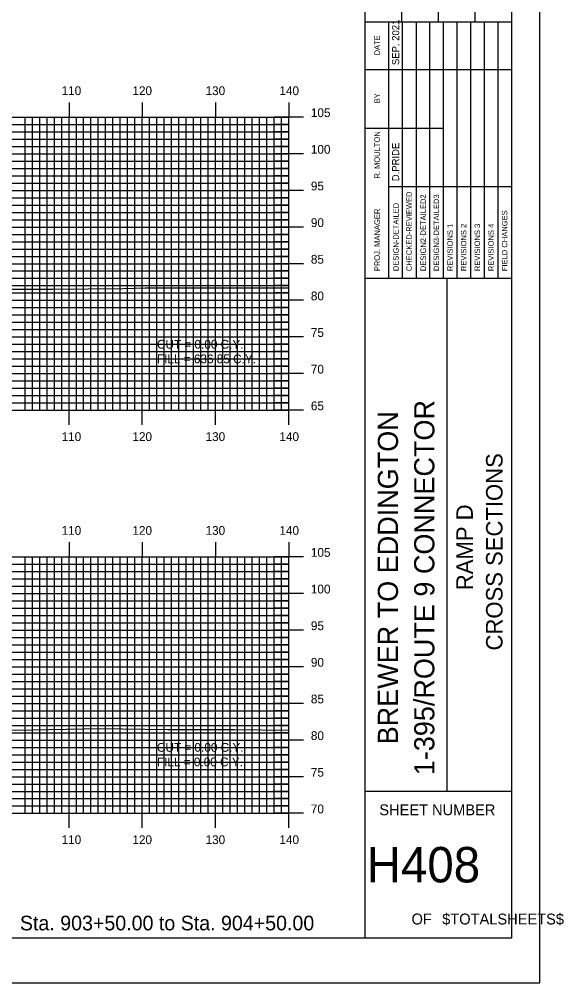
# Model space of a CAD drawing. Extents: x 857110 to 857453, y 364765 to 364985.
# Drawn here: x 857379 to 857453.3, y 364765.2 to 364896.6 of the extents above; entities that cross this region are included whole.
import ezdxf

# ---------------------------------------------------------------- set-up
doc = ezdxf.new("R2010")
doc.units = 0
for name, color, linetype in [('BORDER', 7, 'Continuous'), ('D_Text_Standard', 7, 'Continuous'), ('H_V ANNOTATION', 7, 'Continuous'), ('MAJOR', 7, 'Continuous'), ('MINOR', 7, 'Continuous'), ('PLOT BOUNDARY', 7, 'Continuous'), ('S_Roadway_Centerline', 7, 'Continuous')]:
    doc.layers.add(name, color=color, linetype=linetype)

msp = doc.modelspace()

# ---------------------------------------------------------------- linework, layer by layer
at = {"layer": 'BORDER'}
for p, q in [((857426.19, 364771.3), (857426.19, 364981.3)), ((857431.19, 364896.31), (857431.19, 364913.6)), ((857436.19, 364896.31), (857436.19, 364913.6)), ((857441.19, 364896.31), (857441.19, 364913.6)), ((857426.19, 364896.31), (857446.19, 364896.31)), ((857426.19, 364861.31), (857446.19, 364861.31)), ((857437.38, 364791.31), (857437.38, 364861.31)), ((857426.19, 364791.31), (857446.19, 364791.31))]:
    msp.add_line(p, q, dxfattribs=at)
msp.add_lwpolyline([(857126.19, 364771.3), (857446.19, 364771.3), (857446.19, 364981.3), (857126.19, 364981.3)], close=True, dxfattribs=at)
for points in [[(857429.42, 364889.81), (857429.42, 364896.31)], [(857431.29, 364861.31), (857431.29, 364896.31)], [(857433.15, 364896.31), (857433.15, 364861.31)], [(857435.02, 364861.31), (857435.02, 364896.31)], [(857436.88, 364861.31), (857436.88, 364896.31)], [(857438.74, 364861.31), (857438.74, 364896.31)], [(857440.61, 364861.31), (857440.61, 364896.31)], [(857442.47, 364861.31), (857442.47, 364896.31)], [(857444.33, 364861.31), (857444.33, 364896.31)], [(857429.43, 364861.31), (857429.43, 364894.9)], [(857426.19, 364889.81), (857446.19, 364889.81)], [(857426.19, 364881.81), (857429.43, 364881.81)], [(857429.42, 364881.81), (857436.88, 364881.81)], [(857429.42, 364873.81), (857446.19, 364873.81)]]:
    msp.add_lwpolyline(points, dxfattribs=at)
at = {"layer": 'MAJOR'}
for p, q in [((857385.79, 364885.31), (857385.79, 364883.3)), ((857395.79, 364885.31), (857395.79, 364883.3)), ((857405.79, 364885.31), (857405.79, 364883.3)), ((857415.79, 364885.31), (857415.79, 364883.3)), ((857135.79, 364883.3), (857415.79, 364883.3)), ((857135.79, 364883.3), (857415.79, 364883.3)), ((857385.79, 364843.3), (857385.79, 364883.3)), ((857395.79, 364843.3), (857395.79, 364883.3)), ((857405.79, 364843.3), (857405.79, 364883.3)), ((857417.8, 364883.3), (857413.79, 364883.3)), ((857415.79, 364843.3), (857415.79, 364883.3)), ((857415.79, 364843.3), (857415.79, 364883.3)), ((857135.79, 364878.3), (857415.79, 364878.3)), ((857417.8, 364878.3), (857413.79, 364878.3)), ((857135.79, 364873.3), (857415.79, 364873.3)), ((857417.8, 364873.3), (857413.79, 364873.3)), ((857135.79, 364868.3), (857415.79, 364868.3)), ((857417.8, 364868.3), (857413.79, 364868.3)), ((857135.79, 364863.3), (857415.79, 364863.3)), ((857417.8, 364863.3), (857413.79, 364863.3)), ((857135.79, 364858.3), (857415.79, 364858.3)), ((857417.8, 364858.3), (857413.79, 364858.3)), ((857135.79, 364853.3), (857415.79, 364853.3)), ((857417.8, 364853.3), (857413.79, 364853.3)), ((857135.79, 364848.3), (857415.79, 364848.3)), ((857417.8, 364848.3), (857413.79, 364848.3)), ((857135.79, 364843.3), (857415.79, 364843.3)), ((857135.79, 364843.3), (857415.79, 364843.3)), ((857385.79, 364841.3), (857385.79, 364843.3)), ((857395.79, 364841.3), (857395.79, 364843.3)), ((857405.79, 364841.3), (857405.79, 364843.3)), ((857417.8, 364843.3), (857413.79, 364843.3)), ((857415.79, 364841.3), (857415.79, 364843.3)), ((857385.79, 364825.31), (857385.79, 364823.3)), ((857395.79, 364825.31), (857395.79, 364823.3)), ((857405.79, 364825.31), (857405.79, 364823.3)), ((857415.79, 364825.31), (857415.79, 364823.3)), ((857135.79, 364823.3), (857415.79, 364823.3)), ((857135.79, 364823.3), (857415.79, 364823.3)), ((857385.79, 364788.3), (857385.79, 364823.3)), ((857395.79, 364788.3), (857395.79, 364823.3)), ((857405.79, 364788.3), (857405.79, 364823.3)), ((857417.8, 364823.3), (857413.79, 364823.3)), ((857415.79, 364788.3), (857415.79, 364823.3)), ((857415.79, 364788.3), (857415.79, 364823.3)), ((857135.79, 364818.3), (857415.79, 364818.3)), ((857417.8, 364818.3), (857413.79, 364818.3)), ((857135.79, 364813.3), (857415.79, 364813.3)), ((857417.8, 364813.3), (857413.79, 364813.3)), ((857135.79, 364808.3), (857415.79, 364808.3)), ((857417.8, 364808.3), (857413.79, 364808.3)), ((857135.79, 364803.3), (857415.79, 364803.3)), ((857417.8, 364803.3), (857413.79, 364803.3)), ((857135.79, 364798.3), (857415.79, 364798.3)), ((857417.8, 364798.3), (857413.79, 364798.3)), ((857135.79, 364793.3), (857415.79, 364793.3)), ((857417.8, 364793.3), (857413.79, 364793.3)), ((857135.79, 364788.3), (857415.79, 364788.3)), ((857135.79, 364788.3), (857415.79, 364788.3)), ((857385.79, 364786.3), (857385.79, 364788.3)), ((857395.79, 364786.3), (857395.79, 364788.3)), ((857405.79, 364786.3), (857405.79, 364788.3)), ((857417.8, 364788.3), (857413.79, 364788.3)), ((857415.79, 364786.3), (857415.79, 364788.3))]:
    msp.add_line(p, q, dxfattribs=at)
at = {"layer": 'MINOR'}
for p, q in [((857379.79, 364843.3), (857379.79, 364883.3)), ((857380.79, 364843.3), (857380.79, 364883.3)), ((857381.79, 364843.3), (857381.79, 364883.3)), ((857382.79, 364843.3), (857382.79, 364883.3)), ((857383.79, 364843.3), (857383.79, 364883.3)), ((857384.79, 364843.3), (857384.79, 364883.3)), ((857386.79, 364843.3), (857386.79, 364883.3)), ((857387.79, 364843.3), (857387.79, 364883.3)), ((857388.79, 364843.3), (857388.79, 364883.3)), ((857389.79, 364843.3), (857389.79, 364883.3)), ((857390.79, 364843.3), (857390.79, 364883.3)), ((857391.79, 364843.3), (857391.79, 364883.3)), ((857392.79, 364843.3), (857392.79, 364883.3)), ((857393.79, 364843.3), (857393.79, 364883.3)), ((857394.79, 364843.3), (857394.79, 364883.3)), ((857396.79, 364843.3), (857396.79, 364883.3)), ((857397.79, 364843.3), (857397.79, 364883.3)), ((857398.79, 364843.3), (857398.79, 364883.3)), ((857399.79, 364843.3), (857399.79, 364883.3)), ((857400.79, 364843.3), (857400.79, 364883.3)), ((857401.79, 364843.3), (857401.79, 364883.3)), ((857402.79, 364843.3), (857402.79, 364883.3)), ((857403.79, 364843.3), (857403.79, 364883.3)), ((857404.79, 364843.3), (857404.79, 364883.3)), ((857406.79, 364843.3), (857406.79, 364883.3)), ((857407.79, 364843.3), (857407.79, 364883.3)), ((857408.79, 364843.3), (857408.79, 364883.3)), ((857409.79, 364843.3), (857409.79, 364883.3)), ((857410.79, 364843.3), (857410.79, 364883.3)), ((857411.79, 364843.3), (857411.79, 364883.3)), ((857412.79, 364843.3), (857412.79, 364883.3)), ((857413.79, 364843.3), (857413.79, 364883.3)), ((857414.79, 364843.3), (857414.79, 364883.3)), ((857135.79, 364882.3), (857415.79, 364882.3)), ((857415.79, 364882.3), (857413.79, 364882.3)), ((857135.79, 364881.3), (857415.79, 364881.3)), ((857135.79, 364880.3), (857415.79, 364880.3)), ((857415.79, 364881.3), (857413.79, 364881.3)), ((857415.79, 364880.3), (857413.79, 364880.3)), ((857135.79, 364879.3), (857415.79, 364879.3)), ((857415.79, 364879.3), (857413.79, 364879.3)), ((857135.79, 364877.3), (857415.79, 364877.3)), ((857135.79, 364876.3), (857415.79, 364876.3)), ((857415.79, 364877.3), (857413.79, 364877.3)), ((857415.79, 364876.3), (857413.79, 364876.3)), ((857135.79, 364875.3), (857415.79, 364875.3)), ((857415.79, 364875.3), (857413.79, 364875.3)), ((857135.79, 364874.3), (857415.79, 364874.3)), ((857415.79, 364874.3), (857413.79, 364874.3)), ((857135.79, 364872.3), (857415.79, 364872.3)), ((857415.79, 364872.3), (857413.79, 364872.3)), ((857135.79, 364871.3), (857415.79, 364871.3)), ((857415.79, 364871.3), (857413.79, 364871.3)), ((857135.79, 364870.3), (857415.79, 364870.3)), ((857415.79, 364870.3), (857413.79, 364870.3)), ((857135.79, 364869.3), (857415.79, 364869.3)), ((857415.79, 364869.3), (857413.79, 364869.3)), ((857135.79, 364867.3), (857415.79, 364867.3)), ((857415.79, 364867.3), (857413.79, 364867.3)), ((857135.79, 364866.3), (857415.79, 364866.3)), ((857415.79, 364866.3), (857413.79, 364866.3)), ((857135.79, 364865.3), (857415.79, 364865.3)), ((857135.79, 364864.3), (857415.79, 364864.3)), ((857415.79, 364865.3), (857413.79, 364865.3)), ((857415.79, 364864.3), (857413.79, 364864.3)), ((857135.79, 364862.3), (857415.79, 364862.3)), ((857415.79, 364862.3), (857413.79, 364862.3)), ((857135.79, 364861.3), (857415.79, 364861.3)), ((857135.79, 364860.3), (857415.79, 364860.3)), ((857415.79, 364861.3), (857413.79, 364861.3)), ((857415.79, 364860.3), (857413.79, 364860.3)), ((857135.79, 364859.3), (857415.79, 364859.3)), ((857415.79, 364859.3), (857413.79, 364859.3)), ((857135.79, 364857.3), (857415.79, 364857.3)), ((857415.79, 364857.3), (857413.79, 364857.3)), ((857135.79, 364856.3), (857415.79, 364856.3)), ((857135.79, 364855.3), (857415.79, 364855.3)), ((857415.79, 364856.3), (857413.79, 364856.3)), ((857415.79, 364855.3), (857413.79, 364855.3)), ((857135.79, 364854.3), (857415.79, 364854.3)), ((857415.79, 364854.3), (857413.79, 364854.3)), ((857135.79, 364852.3), (857415.79, 364852.3)), ((857135.79, 364851.3), (857415.79, 364851.3)), ((857415.79, 364852.3), (857413.79, 364852.3)), ((857415.79, 364851.3), (857413.79, 364851.3)), ((857135.79, 364850.3), (857415.79, 364850.3)), ((857415.79, 364850.3), (857413.79, 364850.3)), ((857135.79, 364849.3), (857415.79, 364849.3)), ((857415.79, 364849.3), (857413.79, 364849.3)), ((857135.79, 364847.3), (857415.79, 364847.3)), ((857415.79, 364847.3), (857413.79, 364847.3)), ((857135.79, 364846.3), (857415.79, 364846.3)), ((857415.79, 364846.3), (857413.79, 364846.3)), ((857135.79, 364845.3), (857415.79, 364845.3)), ((857415.79, 364845.3), (857413.79, 364845.3)), ((857135.79, 364844.3), (857415.79, 364844.3)), ((857415.79, 364844.3), (857413.79, 364844.3)), ((857135.79, 364822.3), (857415.79, 364822.3)), ((857379.79, 364788.3), (857379.79, 364823.3)), ((857380.79, 364788.3), (857380.79, 364823.3)), ((857381.79, 364788.3), (857381.79, 364823.3)), ((857382.79, 364788.3), (857382.79, 364823.3)), ((857383.79, 364788.3), (857383.79, 364823.3)), ((857384.79, 364788.3), (857384.79, 364823.3)), ((857386.79, 364788.3), (857386.79, 364823.3)), ((857387.79, 364788.3), (857387.79, 364823.3)), ((857388.79, 364788.3), (857388.79, 364823.3)), ((857389.79, 364788.3), (857389.79, 364823.3)), ((857390.79, 364788.3), (857390.79, 364823.3)), ((857391.79, 364788.3), (857391.79, 364823.3)), ((857392.79, 364788.3), (857392.79, 364823.3)), ((857393.79, 364788.3), (857393.79, 364823.3)), ((857394.79, 364788.3), (857394.79, 364823.3)), ((857396.79, 364788.3), (857396.79, 364823.3)), ((857397.79, 364788.3), (857397.79, 364823.3)), ((857398.79, 364788.3), (857398.79, 364823.3)), ((857399.79, 364788.3), (857399.79, 364823.3)), ((857400.79, 364788.3), (857400.79, 364823.3)), ((857401.79, 364788.3), (857401.79, 364823.3)), ((857402.79, 364788.3), (857402.79, 364823.3)), ((857403.79, 364788.3), (857403.79, 364823.3)), ((857404.79, 364788.3), (857404.79, 364823.3)), ((857406.79, 364788.3), (857406.79, 364823.3)), ((857407.79, 364788.3), (857407.79, 364823.3)), ((857408.79, 364788.3), (857408.79, 364823.3)), ((857409.79, 364788.3), (857409.79, 364823.3)), ((857410.79, 364788.3), (857410.79, 364823.3)), ((857411.79, 364788.3), (857411.79, 364823.3)), ((857412.79, 364788.3), (857412.79, 364823.3)), ((857413.79, 364788.3), (857413.79, 364823.3)), ((857415.79, 364822.3), (857413.79, 364822.3)), ((857414.79, 364788.3), (857414.79, 364823.3)), ((857135.79, 364821.3), (857415.79, 364821.3)), ((857415.79, 364821.3), (857413.79, 364821.3)), ((857135.79, 364820.3), (857415.79, 364820.3)), ((857415.79, 364820.3), (857413.79, 364820.3)), ((857135.79, 364819.3), (857415.79, 364819.3)), ((857415.79, 364819.3), (857413.79, 364819.3)), ((857135.79, 364817.3), (857415.79, 364817.3)), ((857415.79, 364817.3), (857413.79, 364817.3)), ((857135.79, 364816.3), (857415.79, 364816.3)), ((857415.79, 364816.3), (857413.79, 364816.3)), ((857135.79, 364815.3), (857415.79, 364815.3)), ((857135.79, 364814.3), (857415.79, 364814.3)), ((857415.79, 364815.3), (857413.79, 364815.3)), ((857415.79, 364814.3), (857413.79, 364814.3)), ((857135.79, 364812.3), (857415.79, 364812.3)), ((857415.79, 364812.3), (857413.79, 364812.3)), ((857135.79, 364811.3), (857415.79, 364811.3)), ((857415.79, 364811.3), (857413.79, 364811.3)), ((857135.79, 364810.3), (857415.79, 364810.3)), ((857135.79, 364809.3), (857415.79, 364809.3)), ((857415.79, 364810.3), (857413.79, 364810.3)), ((857415.79, 364809.3), (857413.79, 364809.3)), ((857135.79, 364807.3), (857415.79, 364807.3)), ((857415.79, 364807.3), (857413.79, 364807.3)), ((857135.79, 364806.3), (857415.79, 364806.3)), ((857135.79, 364805.3), (857415.79, 364805.3)), ((857415.79, 364806.3), (857413.79, 364806.3)), ((857415.79, 364805.3), (857413.79, 364805.3)), ((857135.79, 364804.3), (857415.79, 364804.3)), ((857415.79, 364804.3), (857413.79, 364804.3)), ((857135.79, 364802.3), (857415.79, 364802.3)), ((857135.79, 364801.3), (857415.79, 364801.3)), ((857415.79, 364802.3), (857413.79, 364802.3)), ((857415.79, 364801.3), (857413.79, 364801.3)), ((857135.79, 364800.3), (857415.79, 364800.3)), ((857415.79, 364800.3), (857413.79, 364800.3)), ((857135.79, 364799.3), (857415.79, 364799.3)), ((857415.79, 364799.3), (857413.79, 364799.3)), ((857135.79, 364797.3), (857415.79, 364797.3)), ((857415.79, 364797.3), (857413.79, 364797.3)), ((857135.79, 364796.3), (857415.79, 364796.3)), ((857415.79, 364796.3), (857413.79, 364796.3)), ((857135.79, 364795.3), (857415.79, 364795.3)), ((857415.79, 364795.3), (857413.79, 364795.3)), ((857135.79, 364794.3), (857415.79, 364794.3)), ((857415.79, 364794.3), (857413.79, 364794.3)), ((857135.79, 364792.3), (857415.79, 364792.3)), ((857415.79, 364792.3), (857413.79, 364792.3)), ((857135.79, 364791.3), (857415.79, 364791.3)), ((857415.79, 364791.3), (857413.79, 364791.3)), ((857135.79, 364790.3), (857415.79, 364790.3)), ((857415.79, 364790.3), (857413.79, 364790.3)), ((857135.79, 364789.3), (857415.79, 364789.3)), ((857415.79, 364789.3), (857413.79, 364789.3))]:
    msp.add_line(p, q, dxfattribs=at)
at = {"layer": 'PLOT BOUNDARY'}
msp.add_lwpolyline([(857110.01, 364765.18), (857450.01, 364765.18), (857450.01, 364985.18), (857110.01, 364985.18)], close=True, dxfattribs=at)
at = {"layer": 'S_Roadway_Centerline'}
for points in [[(857305.39, 364858.78), (857320.95, 364859.89), (857321.58, 364859.9), (857339.57, 364860.34), (857354.51, 364859.89), (857357.85, 364859.8), (857359.08, 364859.8), (857361.86, 364859.78), (857375.05, 364859.83), (857383.56, 364859.84), (857393.24, 364859.93), (857396.16, 364860.02), (857404.57, 364860.02), (857409.54, 364860), (857411.24, 364859.98), (857415.13, 364860.01), (857415.79, 364860.02)], [(857316.68, 364799.43), (857325.33, 364799.67), (857334.44, 364799.52), (857337.4, 364799.51), (857342.96, 364799.57), (857349.21, 364799.66), (857352.55, 364799.65), (857362.29, 364799.83), (857370.85, 364799.69), (857378.51, 364799.66), (857390.01, 364799.88), (857399.29, 364799.73), (857408.36, 364799.74), (857415.79, 364799.63)]]:
    msp.add_lwpolyline(points, dxfattribs=at)

# ---------------------------------------------------------------- texts
at = {"layer": 'BORDER'}
for s, height, p in [('SEP. 2021', 0.969, (857430.84, 364890.4)), ('DATE', 0.743, (857428.2, 364891.72)), ('BY', 0.743, (857428.2, 364885.18)), ('R. MOULTON', 0.745, (857428.2, 364874.91)), ('D.PRIDE', 0.969, (857430.84, 364874.55)), ('CHECKED-REVIEWED', 0.7455, (857432.56, 364862.28)), ('DESIGN2-DETAILED2', 0.7455, (857434.49, 364862.28)), ('DESIGN3-DETAILED3', 0.7455, (857436.28, 364862.28)), ('DESIGN-DETAILED', 0.7455, (857430.77, 364862.28)), ('PROJ. MANAGER', 0.7455, (857428.2, 364862.28)), ('FIELD CHANGES', 0.7455, (857445.6, 364862.28)), ('REVISIONS 1', 0.7455, (857438.15, 364862.28)), ('REVISIONS 2', 0.7455, (857440.01, 364862.28)), ('REVISIONS 3', 0.7455, (857441.87, 364862.28)), ('REVISIONS 4', 0.7455, (857443.74, 364862.28)), ('1-395/ROUTE 9 CONNECTOR', 2.7557, (857435.64, 364793.5)), ('BREWER TO EDDINGTON', 2.7557, (857430.68, 364797.71)), ('CROSS SECTIONS', 2.25, (857444.94, 364810.52)), ('RAMP D', 2.25, (857440.89, 364818.75))]:
    msp.add_text(s, height=height, rotation=90, dxfattribs=at).set_placement(p)
for s, height, p in [('SHEET NUMBER', 1.4905, (857428.13, 364788.03)), ('H408', 4.839, (857426.41, 364778.87)), ('OF', 1.491, (857432.53, 364773.13)), ('$TOTALSHEETS$', 1.4905, (857436.71, 364773.13))]:
    msp.add_text(s, height=height, dxfattribs=at).set_placement(p)
at = {"layer": 'D_Text_Standard'}
for s, p in [('CUT = 0.00 C.Y.', (857397.79, 364851.7)), ('FILL = 636.85 C.Y.', (857397.79, 364849.71)), ('CUT = 0.00 C.Y.', (857397.79, 364796.7)), ('FILL = 0.00 C.Y.', (857397.79, 364794.71))]:
    msp.add_text(s, height=1.2, dxfattribs=at).set_placement(p)
at = {"layer": 'H_V ANNOTATION'}
for s, height, p in [('110', 1.2, (857384.78, 364886.3)), ('120', 1.2, (857394.44, 364886.3)), ('130', 1.2, (857404.42, 364886.3)), ('140', 1.2, (857414.5, 364886.3)), ('105', 1.2, (857418.79, 364883.3)), ('100', 1.2, (857418.79, 364878.3)), ('95', 1.2, (857418.79, 364873.3)), ('90', 1.2, (857418.79, 364868.3)), ('85', 1.2, (857418.79, 364863.3)), ('80', 1.2, (857418.79, 364858.3)), ('75', 1.2, (857418.79, 364853.3)), ('70', 1.2, (857418.79, 364848.3)), ('65', 1.2, (857418.79, 364843.3)), ('110', 1.2, (857384.78, 364839.1)), ('120', 1.2, (857394.44, 364839.1)), ('130', 1.2, (857404.42, 364839.1)), ('140', 1.2, (857414.5, 364839.1)), ('110', 1.2, (857384.78, 364826.3)), ('120', 1.2, (857394.44, 364826.3)), ('130', 1.2, (857404.42, 364826.3)), ('140', 1.2, (857414.5, 364826.3)), ('105', 1.2, (857418.79, 364823.3)), ('100', 1.2, (857418.79, 364818.3)), ('95', 1.2, (857418.79, 364813.3)), ('90', 1.2, (857418.79, 364808.3)), ('85', 1.2, (857418.79, 364803.3)), ('80', 1.2, (857418.79, 364798.3)), ('75', 1.2, (857418.79, 364793.3)), ('70', 1.2, (857418.79, 364788.3)), ('110', 1.2, (857384.78, 364784.1)), ('120', 1.2, (857394.44, 364784.1)), ('130', 1.2, (857404.42, 364784.1)), ('140', 1.2, (857414.5, 364784.1)), ('Sta. 903+50.00 to Sta. 904+50.00', 2.0004, (857379.09, 364772.33))]:
    msp.add_text(s, height=height, dxfattribs=at).set_placement(p)

doc.saveas('drawing.dxf')
